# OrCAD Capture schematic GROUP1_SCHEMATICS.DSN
size C; title: Group1; rev: 1; note: Item Tracker
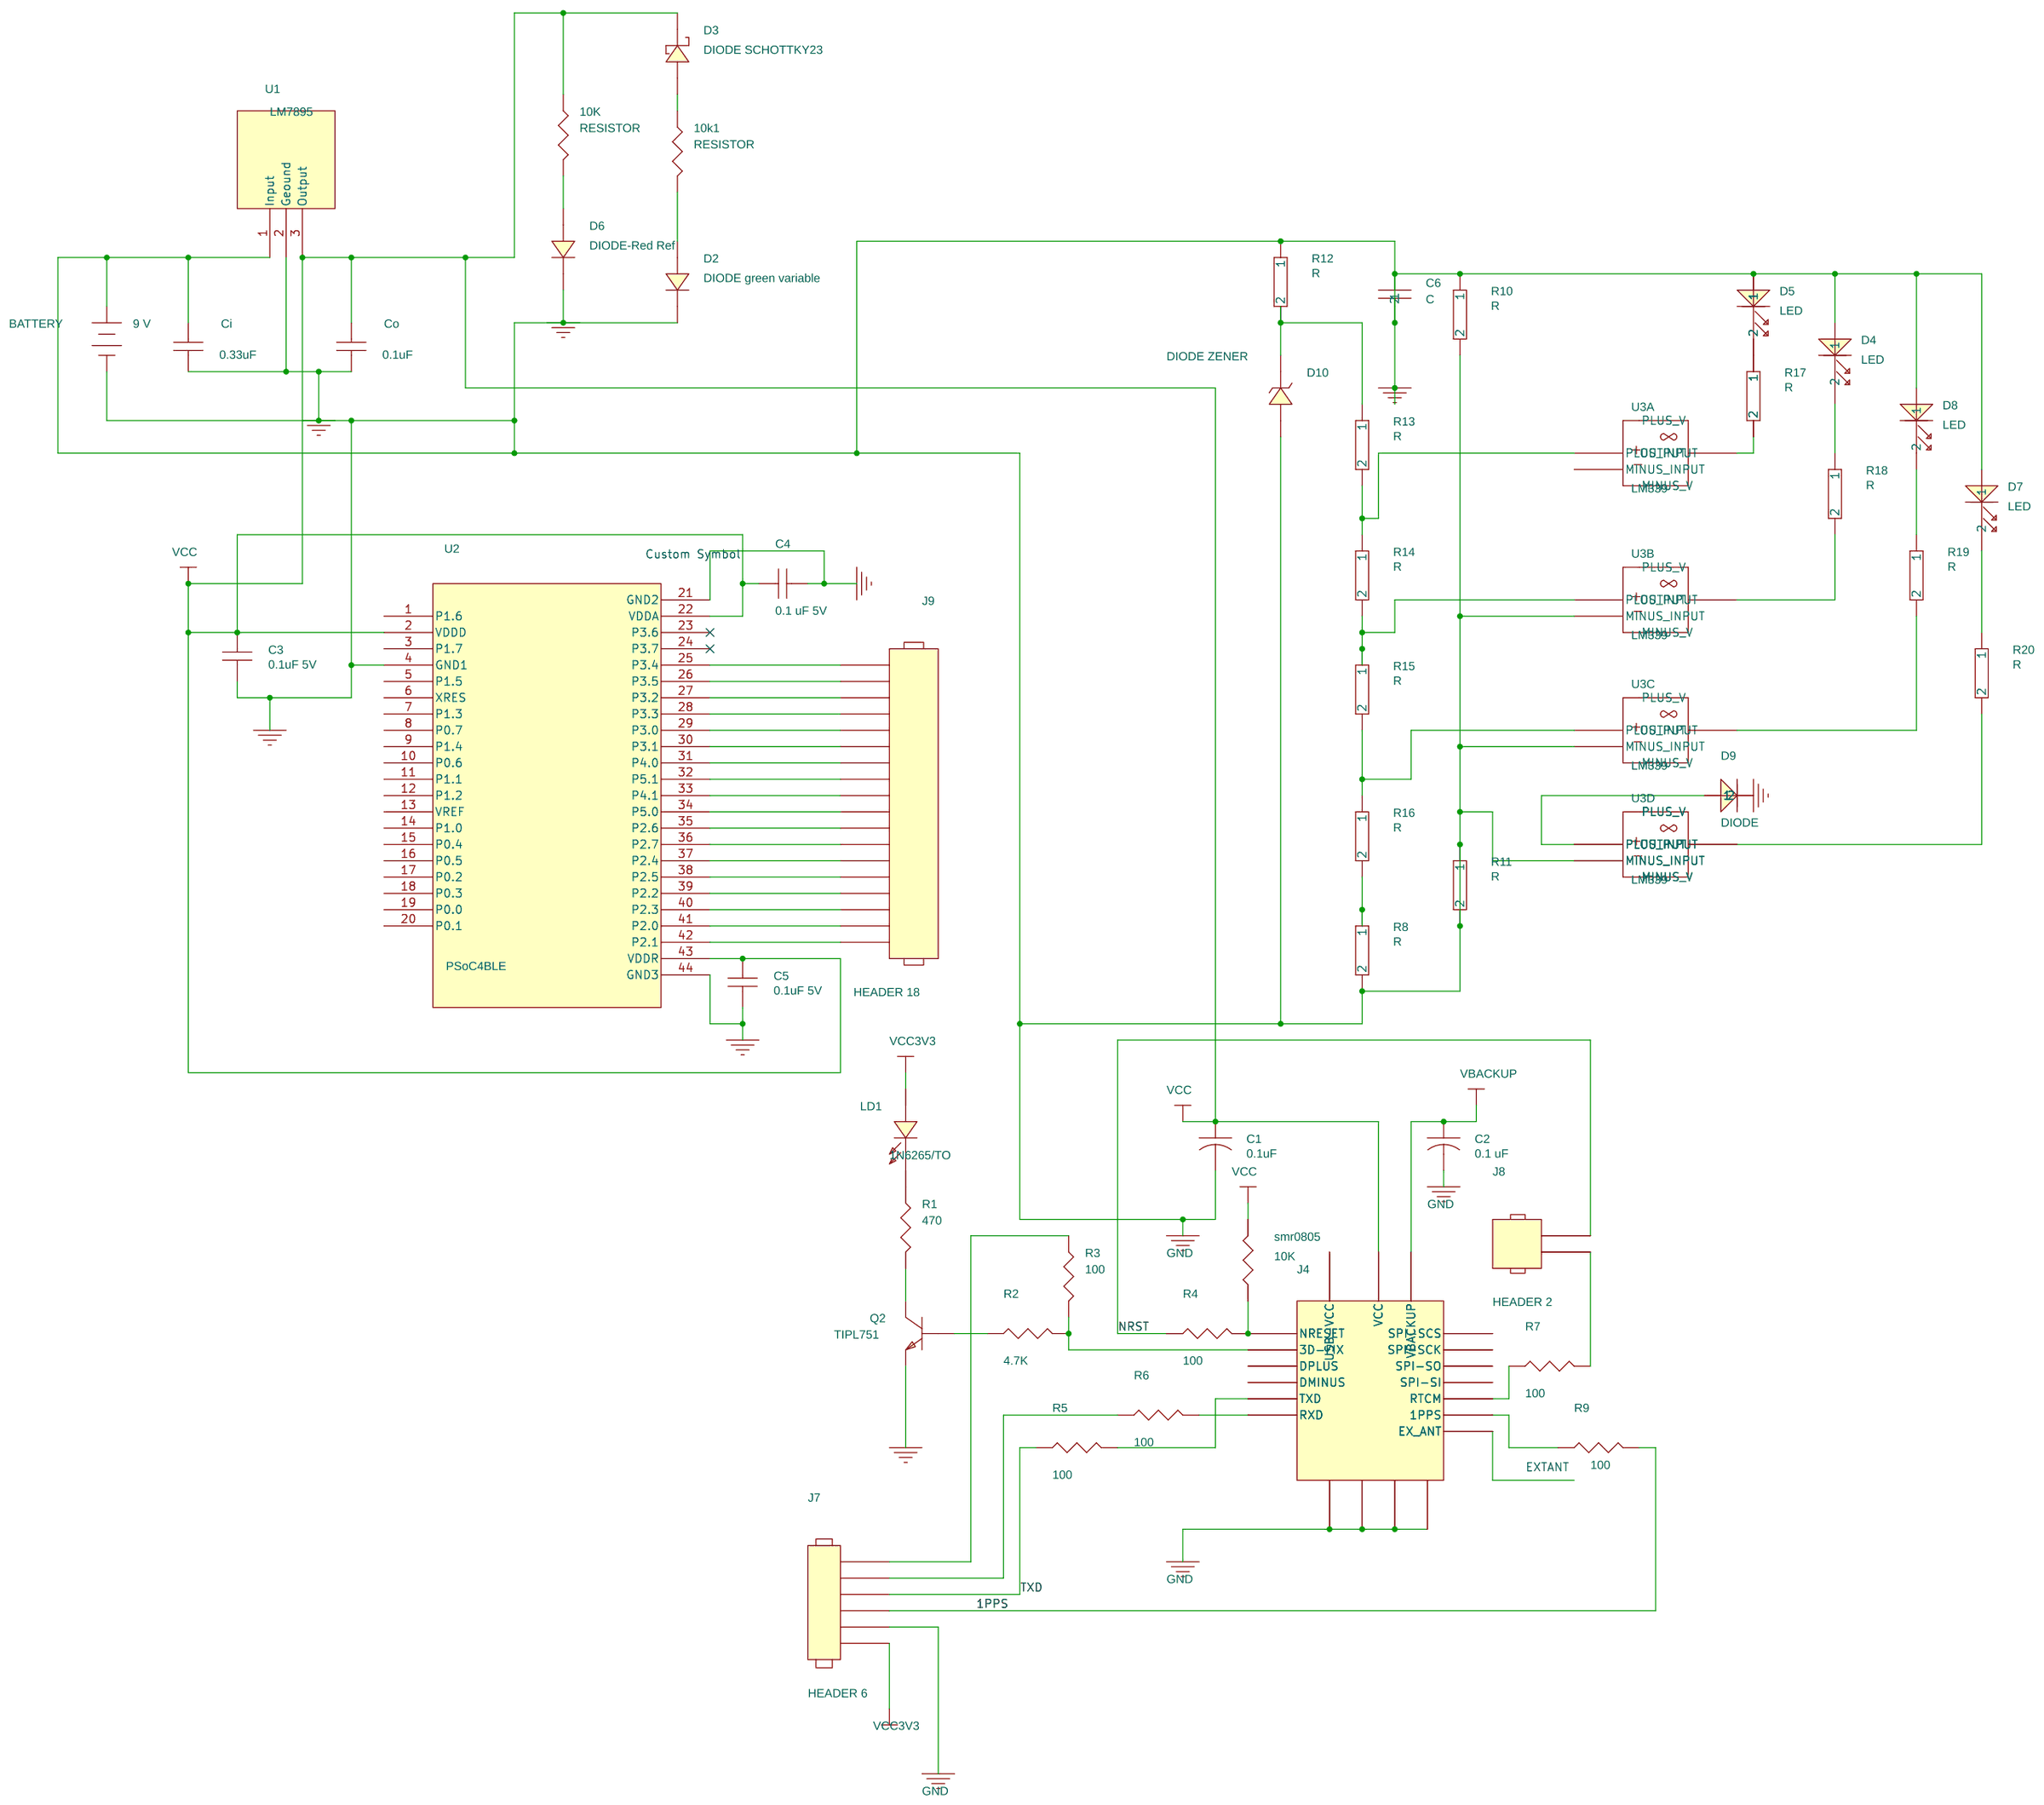
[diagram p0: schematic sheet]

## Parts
9 V  BATTERY
10K  RESISTOR
10k1  RESISTOR
C1  0.1uF  [smc0805]
C2  0.1 uF  [smc0805]
C3  0.1uF 5V  [Cap1]
C4  0.1 uF 5V  [Cap1]
C5  0.1uF 5V  [Cap1]
C6  C
Ci  0.33uF  [H2]
Co  0.1uF  [H2]
D2  DIODE green variable
D3  DIODE SCHOTTKY23
D4  LED
D5  LED
D6  DIODE-Red Ref
D7  LED
D8  LED
D9  DIODE
D10  DIODE ZENER
J4  CON20A  [PLCC20]
J7  HEADER 6  [sip6]
J8  HEADER 2  [sip2]
J9  HEADER 18  [Header18]
LD1  1N6265/TO  [DAX2850X225062]
Q2  TIPL751  [sip3]
R1  470  [smr0805]
R2  4.7K  [smr0805]
R3  100  [smr0805]
R4  100  [smr0805]
R5  100  [smr0805]
R6  100  [smr0805]
R7  100  [smr0805]
R8  R
R9  100  [smr0805]
R10  R
R11  R
R12  R
R13  R
R14  R
R15  R
R16  R
R17  R
R18  R
R19  R
R20  R
smr0805  10K  [smr0805]
U1  LM7895  [3]
U2  PSoC4BLE  [PSOC4BLE]
U3  LM339  (sections A,B,C,D)

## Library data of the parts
9 V = BATTERY
10K 10k1 R1-R7 R9 smr0805 = RESISTOR
C1 C2 = CAPACITOR
C3-C5 Ci Co = CAP_NP
C6 = C
D2 D6 = DIODE_v2
D3 = DIODE_SCHOTTKY23
D4 = LED_1
D5 = LED
D7 = LED_3
D8 = LED_2
D9 = DIODE
D10 = DIODE_ZENER
J4 = CON20A_7
J7 = HEADER_6
J8 = HEADER_2
J9 = HEADER_18
LD1 = 1N6265_TO_0
Q2 = TIPL751
R8 = R
R10 = R_7
R11 = R_6
R12 = R_5
R13 = R_4
R14 = R_3
R15 = R_2
R16 = R_1
R17 = R_11
R18 = R_10
R19 = R_9
R20 = R_8
U1 = Linear_regulator
U2 = PSoC4BLE_0
U3 = LM339

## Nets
GND: 9 V.1(+) 9 V.2(-) C1.2 C2.2 C3.2 C4.2 C5.2 C6.1 C6.2 Ci.1 Ci.2 Co.2 D2.1(K) D4.1 D5.1 D6.1(K) D7.1 D8.1 D9.2 D10.2(ANODE) J4.3 J4.8 J4.12 J4.19 J7.5 Q2.3(E) R8.2 R10.1 R10.2 R11.1 R11.2 R12.1 U1.1(Input) U1.2(Geound) U2.4(GND1) U2.21(GND2) U2.44(GND3) U3.6(MINUS_INPUT) U3.8(MINUS_INPUT) U3.10(MINUS_INPUT)
VCC3V3: J7.6 LD1.2(ANODE)
1PPS: J7.4 R9.2
+5 V: 10K.1 C1.1 C3.1 C4.1 C5.1 Co.1 D3.3(K) J4.1(VCC) smr0805.2 U1.3(Output) U2.2(VDDD) U2.22(VDDA) U2.43(VDDR)
MINUS V: U3.12(MINUS_V)
NRST: J8.1 R4.1
PLUS V: U3.3(PLUS_V)
TXD: J7.3 R5.1
VBACKUP: C2.1 J4.4(VBACKUP)
N02243: 10K.2 D6.2(A)
N02247: 10k1.1 D3.2(A)
N02251: 10k1.2 D2.2(A)
N10736: J7.1 R3.1
N10748: J4.5(3D-FIX) R2.2 R3.2
N10760: J4.2(NRESET) R4.2 smr0805.1
N10768: J4.9(TXD) R5.2
N10812: J4.13(1PPS) R9.1
N10820: J4.14(RTCM) R7.1
N11106: J7.2 R6.1
N11128: Q2.2(C) R1.2
N11132: Q2.1(B) R2.1
N15042: J9.18 U2.42(P2.1)
N15046: J9.17 U2.41(P2.0)
N15050: J9.16 U2.40(P2.3)
N15054: J9.15 U2.39(P2.2)
N15058: J9.14 U2.38(P2.5)
N15062: J9.13 U2.37(P2.4)
N15066: J9.12 U2.36(P2.7)
N15070: J9.11 U2.35(P2.6)
N15074: J9.10 U2.34(P5.0)
N15078: J9.9 U2.33(P4.1)
N15082: J9.8 U2.32(P5.1)
N15086: J9.7 U2.31(P4.0)
N15090: J9.6 U2.30(P3.1)
N15094: J9.5 U2.29(P3.0)
N15126: J9.4 U2.28(P3.3)
N15130: J9.3 U2.27(P3.2)
N15134: J9.2 U2.26(P3.5)
N15138: J9.1 U2.25(P3.4)
N16989: J8.2 R7.2
N24721: J4.10(RXD) R6.2
N31027: R17.2 U3.2(OUTPUT)
N31035: R18.2 U3.1(OUTPUT)
N31043: R19.2 U3.14(OUTPUT)
N31051: R20.2 U3.13(OUTPUT)
N31067: D10.1(CATHODE) R12.2 R13.1
N31075: R13.2 R14.1 U3.5(PLUS_INPUT)
N31079: R14.2 R15.1 U3.7(PLUS_INPUT)
N31087: R15.2 R16.1 U3.9(PLUS_INPUT)
N31091: R8.1 R16.2
N31251: D9.1 U3.11(PLUS_INPUT)
N31263: D4.2 R18.1
N31267: D8.2 R19.1
N31271: D7.2 R20.1
N32525: LD1.1(CATHODE) R1.1
N35852: D5.2 R17.1

Not connected (* = marked no-connect by the designer): J4 6(DPLUS) 7(DMINUS) 11(EX_ANT) 15(SPI-SI) 16(SPI-SO) 17(SPI-SCK) 18(SPI-SCS) 20(USB-VCC); U2 1(P1.6) 3(P1.7) 5(P1.5) 6(XRES) 7(P1.3) 8(P0.7) 9(P1.4) 10(P0.6) 11(P1.1) 12(P1.2) 13(VREF) 14(P1.0) 15(P0.4) 16(P0.5) 17(P0.2) 18(P0.3) 19(P0.0) 20(P0.1) 23(P3.6)* 24(P3.7)*; U3 0(MINUS_V) 4(MINUS_INPUT)

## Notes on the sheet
- Custom Symbol
- EXTANT
